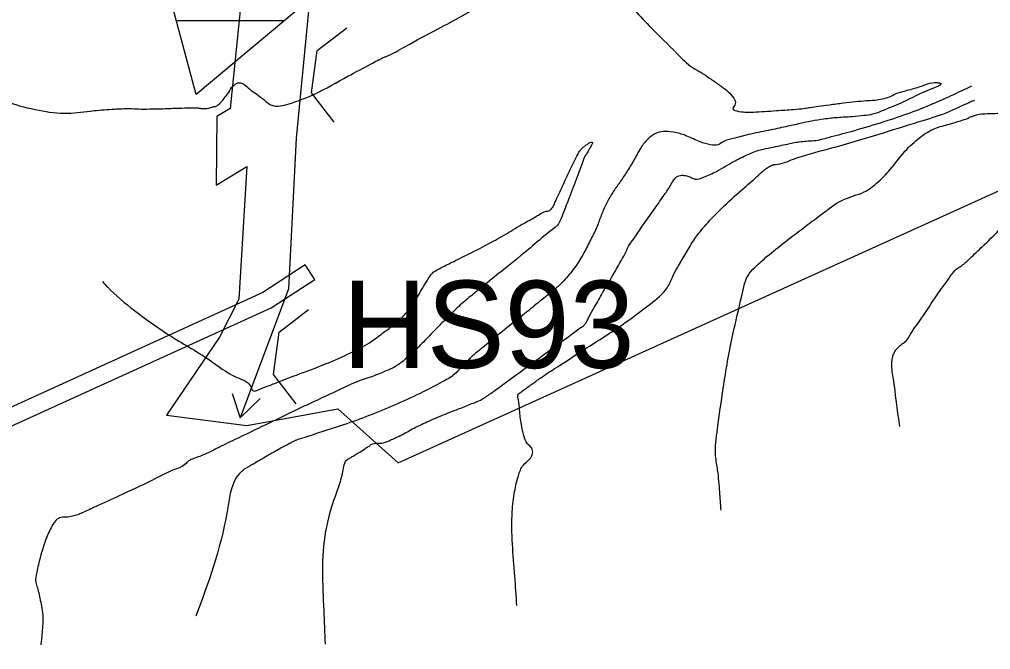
# Model space of a CAD drawing. Extents: x -478464 to -472469, y -1118040 to -1113785.
# Drawn here: x -476628.2 to -476517, y -1115298.9 to -1115226.7 of the extents above; entities that cross this region are included whole.
import ezdxf

# ---------------------------------------------------------------- set-up
doc = ezdxf.new("R2010")
doc.units = 0
for name, color, linetype in [('cestní_příkop_návrh', 7, 'Continuous'), ('hospodářské sjezdy', 7, 'Continuous'), ('meliorace', 7, 'Continuous'), ('ObPÚ', 7, 'Continuous'), ('vodní plochy', 7, 'Continuous'), ('Vrstevnice_hlavni', 7, 'Continuous'), ('Vrstevnice_vedlejsi', 7, 'Continuous')]:
    doc.layers.add(name, color=color, linetype=linetype)

msp = doc.modelspace()

# ---------------------------------------------------------------- linework, layer by layer
at = {"layer": 'cestní_příkop_návrh'}
for p, q in [((-476603.841, -1115269.537), (-476602.946, -1115272.292)), ((-476602.946, -1115272.292), (-476600.666, -1115270.108))]:
    msp.add_line(p, q, dxfattribs=at)
msp.add_lwpolyline([(-476592.877, -1115202.391), (-476596.533, -1115240.263), (-476597.4, -1115257.53), (-476602.946, -1115272.292)], dxfattribs=at)
at = {"layer": 'hospodářské sjezdy'}
for p, q in [((-476594.125, -1115230.214), (-476590.743, -1115227.615)), ((-476594.763, -1115235.058), (-476594.125, -1115230.214)), ((-476592.168, -1115238.443), (-476594.763, -1115235.058)), ((-476598.487, -1115262.482), (-476595.105, -1115259.884)), ((-476599.125, -1115267.326), (-476598.487, -1115262.482)), ((-476596.53, -1115270.711), (-476599.125, -1115267.326))]:
    msp.add_line(p, q, dxfattribs=at)
at = {"layer": 'meliorace'}
msp.add_line((-476610.243, -1115226.781), (-476597.848, -1115226.781), dxfattribs=at)
msp.add_lwpolyline([(-476265.52, -1115104.967), (-476403.006, -1115128.309), (-476504.597, -1115173.139), (-476570.859, -1115204.199), (-476607.972, -1115235.252), (-476617.925, -1115198.125), (-476654.773, -1115224.496), (-476674.466, -1115245.995), (-476697.623, -1115206.296), (-476764.621, -1115246.225), (-476786.533, -1115238.993), (-476834.366, -1115202.796)], dxfattribs=at)
at = {"layer": 'ObPÚ'}
msp.add_lwpolyline([(-476710.61, -1115306.79), (-476720.97, -1115296.87), (-476747.11, -1115275.54), (-476773.1, -1115256.26), (-476753.8, -1115247.81), (-476712.61, -1115214.58), (-476702.4, -1115206.29), (-476694.31, -1115201.09), (-476681.61, -1115192.9), (-476666.84, -1115216.01), (-476654.39, -1115235.55), (-476600.77, -1115204.27), (-476604.1, -1115236.86), (-476605.608, -1115237.767), (-476605.682, -1115245.637), (-476602.18, -1115243.52), (-476602.635, -1115251.11), (-476603.09, -1115258.7), (-476605.31, -1115263.08), (-476611.38, -1115272), (-476602.17, -1115273.19), (-476591.75, -1115271.28), (-476584.84, -1115277.47), (-476500.96, -1115239.45)], dxfattribs=at)
at = {"layer": 'vodní plochy'}
msp.add_line((-476594.388, -1115256.456), (-476595.478, -1115254.78), dxfattribs=at)
for points in [[(-476595.478, -1115254.78), (-476600.348, -1115257.945), (-476635.052, -1115273.742), (-476677.746, -1115288.446), (-476696.055, -1115299.721), (-476699.28, -1115302.082), (-476703.29, -1115304.179), (-476711.241, -1115309.034), (-476722.675, -1115317.101), (-476731.269, -1115323.918), (-476761.118, -1115341.041)], [(-476702.304, -1115305.921), (-476698.22, -1115303.784), (-476694.939, -1115301.383), (-476676.886, -1115290.264), (-476634.31, -1115275.602), (-476599.384, -1115259.703), (-476594.388, -1115256.456)]]:
    msp.add_lwpolyline(points, dxfattribs=at)
at = {"layer": 'Vrstevnice_hlavni'}
for points in [[(-476594.305, -1115212.433), (-476589.149, -1115215.617), (-476587.057, -1115217.102), (-476585.449, -1115218.483), (-476584.326, -1115219.757), (-476583.33, -1115220.543), (-476582.461, -1115220.842), (-476581.718, -1115220.652), (-476580.639, -1115220.531), (-476579.224, -1115220.478), (-476577.473, -1115220.493), (-476575.153, -1115219.941), (-476572.265, -1115218.82), (-476568.807, -1115217.132), (-476563.862, -1115214.927), (-476557.428, -1115212.206), (-476549.506, -1115208.968), (-476543.938, -1115207.11), (-476540.724, -1115206.632), (-476539.864, -1115207.534), (-476539.225, -1115208.173), (-476538.808, -1115208.549), (-476538.612, -1115208.662), (-476538.231, -1115208.929), (-476537.666, -1115209.347), (-476536.917, -1115209.919), (-476536.136, -1115210.322), (-476535.324, -1115210.556), (-476534.48, -1115210.622), (-476533.796, -1115210.6), (-476533.27, -1115210.49), (-476532.903, -1115210.292), (-476532.5, -1115210.146), (-476532.06, -1115210.051), (-476531.583, -1115210.008), (-476530.006, -1115210.808), (-476527.328, -1115212.452), (-476523.549, -1115214.939), (-476520.836, -1115216.731), (-476519.188, -1115217.826), (-476518.606, -1115218.224), (-476517.249, -1115217.693), (-476515.118, -1115216.231), (-476512.211, -1115213.838), (-476509.565, -1115211.741), (-476507.181, -1115209.94), (-476505.057, -1115208.433), (-476503.249, -1115207.018), (-476501.757, -1115205.694), (-476500.581, -1115204.461), (-476497.901, -1115203.024), (-476493.715, -1115201.384), (-476488.024, -1115199.541), (-476482.184, -1115197.217), (-476476.192, -1115194.414), (-476470.051, -1115191.13), (-476465.446, -1115188.696), (-476462.378, -1115187.113), (-476460.846, -1115186.38), (-476458.763, -1115185.408), (-476456.129, -1115184.199), (-476452.943, -1115182.751), (-476451.764, -1115182.586), (-476452.593, -1115183.704), (-476455.428, -1115186.103), (-476457.762, -1115188.052), (-476459.597, -1115189.55), (-476460.93, -1115190.598), (-476464.087, -1115193.012), (-476469.066, -1115196.792), (-476475.868, -1115201.939), (-476480.908, -1115205.899), (-476484.185, -1115208.674), (-476485.7, -1115210.262), (-476486.849, -1115211.737), (-476487.632, -1115213.098), (-476488.05, -1115214.346), (-476489.152, -1115215.928), (-476490.94, -1115217.844), (-476493.413, -1115220.094), (-476495.2, -1115221.825), (-476496.301, -1115223.037), (-476496.715, -1115223.731), (-476496.992, -1115224.194), (-476497.13, -1115224.425), (-476497.131, -1115224.425), (-476497.915, -1115225.146), (-476499.483, -1115226.587), (-476501.835, -1115228.749), (-476503.657, -1115230.272), (-476504.951, -1115231.155), (-476506.478, -1115231.643)], [(-476532.986, -1115239.492), (-476529.594, -1115238.495), (-476526.551, -1115237.472), (-476523.857, -1115236.425), (-476519.167, -1115234.282)], [(-476593.169, -1115298.22), (-476593.33, -1115294.354), (-476593.122, -1115285.305), (-476592.031, -1115281.263), (-476591.199, -1115278.509), (-476590.627, -1115277.043), (-476590.314, -1115276.865), (-476589.904, -1115276.621), (-476589.398, -1115276.313), (-476588.795, -1115275.94), (-476588.341, -1115275.65), (-476588.037, -1115275.443), (-476587.881, -1115275.319), (-476587.611, -1115275.238), (-476587.225, -1115275.201), (-476586.725, -1115275.206), (-476585.892, -1115274.939), (-476584.727, -1115274.398), (-476583.23, -1115273.584), (-476581.554, -1115272.777), (-476579.698, -1115271.976), (-476577.664, -1115271.182), (-476576.234, -1115270.611), (-476575.407, -1115270.264), (-476575.184, -1115270.141), (-476574.915, -1115269.974), (-476574.601, -1115269.763), (-476574.242, -1115269.509), (-476572.91, -1115268.538), (-476570.606, -1115266.85), (-476567.33, -1115264.446), (-476565.075, -1115262.798), (-476563.843, -1115261.906), (-476563.633, -1115261.77), (-476563.42, -1115261.532), (-476563.205, -1115261.193), (-476562.988, -1115260.753), (-476562.395, -1115259.684), (-476561.428, -1115257.985), (-476560.085, -1115255.656), (-476559.161, -1115254.025), (-476558.654, -1115253.092), (-476558.566, -1115252.857), (-476558.004, -1115251.986), (-476556.968, -1115250.48), (-476555.459, -1115248.339), (-476554.354, -1115246.737), (-476553.653, -1115245.675), (-476553.355, -1115245.151), (-476553.038, -1115244.784), (-476552.702, -1115244.573), (-476552.345, -1115244.517), (-476551.924, -1115244.561), (-476551.439, -1115244.705), (-476550.889, -1115244.949), (-476549.877, -1115244.74), (-476548.405, -1115244.078), (-476546.472, -1115242.962), (-476544.787, -1115242.135), (-476543.349, -1115241.596), (-476542.158, -1115241.344), (-476541.144, -1115241.128), (-476540.305, -1115240.947), (-476539.641, -1115240.801), (-476538.91, -1115240.685), (-476538.112, -1115240.6), (-476537.245, -1115240.545), (-476535.537, -1115240.176), (-476532.986, -1115239.492)]]:
    msp.add_spline(points, degree=3, dxfattribs=at)
at = {"layer": 'Vrstevnice_vedlejsi'}
for points in [[(-476527.08, -1115263.803), (-476526.887, -1115263.69), (-476526.162, -1115262.721), (-476524.907, -1115260.894), (-476523.121, -1115258.209), (-476521.764, -1115256.313), (-476520.836, -1115255.206), (-476520.337, -1115254.886), (-476519.366, -1115254.043), (-476517.924, -1115252.676), (-476516.009, -1115250.786), (-476514.302, -1115249.024), (-476512.803, -1115247.392), (-476511.511, -1115245.89), (-476509.929, -1115244.508), (-476508.058, -1115243.246), (-476505.898, -1115242.105), (-476504.014, -1115241.274), (-476502.406, -1115240.753), (-476501.074, -1115240.543), (-476500.026, -1115240.386), (-476499.263, -1115240.283), (-476498.784, -1115240.233), (-476497.172, -1115239.574), (-476494.427, -1115238.305), (-476490.549, -1115236.427), (-476487.653, -1115234.652), (-476485.739, -1115232.982), (-476484.807, -1115231.416), (-476483.874, -1115229.496), (-476482.938, -1115227.221), (-476482, -1115224.593), (-476480.343, -1115222.339), (-476477.964, -1115220.46), (-476474.866, -1115218.956), (-476472.042, -1115216.696), (-476469.492, -1115213.68), (-476467.217, -1115209.908), (-476464.704, -1115205.831), (-476461.955, -1115201.448), (-476458.968, -1115196.76), (-476456.464, -1115193.232), (-476454.442, -1115190.863), (-476452.903, -1115189.654), (-476451.796, -1115188.78), (-476451.122, -1115188.24), (-476450.88, -1115188.036), (-476449.741, -1115187.407), (-476447.705, -1115186.353), (-476444.771, -1115184.875), (-476442.444, -1115183.754), (-476440.723, -1115182.99), (-476439.608, -1115182.582), (-476438.521, -1115182.379), (-476437.462, -1115182.381), (-476436.431, -1115182.589), (-476434.671, -1115182.945), (-476432.182, -1115183.449), (-476428.964, -1115184.102), (-476425.887, -1115183.927), (-476422.953, -1115182.925), (-476420.161, -1115181.095), (-476418.073, -1115179.463), (-476416.69, -1115178.026), (-476416.012, -1115176.786), (-476414.938, -1115175.626), (-476413.47, -1115174.546), (-476411.607, -1115173.546), (-476409.534, -1115172.603), (-476407.252, -1115171.715), (-476404.761, -1115170.883), (-476401.574, -1115169.794), (-476397.69, -1115168.447), (-476393.11, -1115166.843), (-476388.096, -1115165.135), (-476382.647, -1115163.324), (-476376.764, -1115161.408), (-476372.621, -1115160.054), (-476370.219, -1115159.261), (-476369.557, -1115159.028), (-476369.039, -1115158.854), (-476368.663, -1115158.738), (-476368.431, -1115158.68), (-476367.559, -1115158.618), (-476366.047, -1115158.551), (-476363.896, -1115158.479), (-476362.463, -1115158.431), (-476361.747, -1115158.407), (-476361.748, -1115158.407), (-476361.852, -1115158.365), (-476362.059, -1115158.28), (-476362.368, -1115158.152), (-476365.304, -1115157.405), (-476370.868, -1115156.037), (-476379.058, -1115154.05), (-476384.846, -1115152.681), (-476388.232, -1115151.932)], [(-476489.189, -1115228.952), (-476487.784, -1115226.601), (-476486.814, -1115225.003), (-476486.28, -1115224.159), (-476486.181, -1115224.07), (-476485.87, -1115223.275), (-476485.346, -1115221.777), (-476484.609, -1115219.573), (-476483.875, -1115217.426), (-476483.145, -1115215.334), (-476482.419, -1115213.299), (-476481.856, -1115211.903), (-476481.455, -1115211.148), (-476481.216, -1115211.032), (-476480.998, -1115210.858), (-476480.802, -1115210.625), (-476480.626, -1115210.334), (-476480.433, -1115210.02), (-476480.221, -1115209.682), (-476479.991, -1115209.321), (-476476.937, -1115206.803), (-476471.061, -1115202.128), (-476462.362, -1115195.296), (-476456.107, -1115190.356), (-476452.296, -1115187.307), (-476450.93, -1115186.151), (-476449.375, -1115185.055), (-476447.634, -1115184.022), (-476445.704, -1115183.05), (-476443.654, -1115182.122), (-476441.483, -1115181.239), (-476439.191, -1115180.401), (-476436.957, -1115179.984), (-476434.78, -1115179.989), (-476432.661, -1115180.416), (-476430.764, -1115180.799), (-476429.089, -1115181.137), (-476427.637, -1115181.432), (-476426.249, -1115181.353), (-476424.924, -1115180.901), (-476423.664, -1115180.075), (-476422.478, -1115178.892), (-476421.365, -1115177.35), (-476420.326, -1115175.451), (-476418.682, -1115173.674), (-476416.432, -1115172.02), (-476413.578, -1115170.488), (-476411.336, -1115169.353), (-476409.707, -1115168.616), (-476408.69, -1115168.277), (-476405.909, -1115167.314), (-476401.362, -1115165.727), (-476395.051, -1115163.517), (-476390.685, -1115161.991), (-476388.263, -1115161.15), (-476387.785, -1115160.995), (-476387.676, -1115160.76), (-476387.937, -1115160.445), (-476388.566, -1115160.051), (-476389.672, -1115159.551), (-476391.253, -1115158.946), (-476393.311, -1115158.235), (-476397.324, -1115158.048), (-476403.292, -1115158.382), (-476411.216, -1115159.239), (-476416.651, -1115159.884), (-476419.597, -1115160.315), (-476420.053, -1115160.534), (-476420.464, -1115160.658), (-476420.831, -1115160.689), (-476421.152, -1115160.625), (-476422.489, -1115160.766), (-476424.841, -1115161.111), (-476428.208, -1115161.661), (-476433.237, -1115162.642), (-476439.928, -1115164.054), (-476448.281, -1115165.897), (-476454.566, -1115167.346), (-476458.784, -1115168.401), (-476460.934, -1115169.061), (-476463.942, -1115170.404), (-476467.808, -1115172.43), (-476472.532, -1115175.139), (-476478.16, -1115177.4), (-476484.692, -1115179.212), (-476492.129, -1115180.577), (-476497.835, -1115181.563), (-476501.811, -1115182.17), (-476504.055, -1115182.398), (-476506.213, -1115182.703), (-476508.286, -1115183.083), (-476510.272, -1115183.54), (-476513.324, -1115184.328), (-476517.442, -1115185.448), (-476522.626, -1115186.898), (-476526.704, -1115187.828), (-476529.674, -1115188.238)], [(-476651.7, -1115230.934), (-476650.79, -1115230.806), (-476649.193, -1115230.886), (-476646.909, -1115231.176), (-476643.939, -1115231.674), (-476641.52, -1115232.103), (-476639.653, -1115232.461), (-476638.338, -1115232.748), (-476636.207, -1115233.456), (-476633.26, -1115234.585), (-476629.496, -1115236.133), (-476625.982, -1115237.071), (-476622.717, -1115237.398), (-476619.701, -1115237.114), (-476617.342, -1115236.939), (-476615.64, -1115236.874), (-476614.595, -1115236.918), (-476613.302, -1115236.924), (-476611.761, -1115236.892), (-476609.972, -1115236.821), (-476608.635, -1115236.794), (-476607.751, -1115236.811), (-476607.319, -1115236.872), (-476606.93, -1115236.882), (-476606.584, -1115236.842), (-476606.282, -1115236.752), (-476606.035, -1115236.683), (-476605.843, -1115236.637), (-476605.707, -1115236.613), (-476605.533, -1115236.512), (-476605.322, -1115236.336), (-476605.074, -1115236.084), (-476604.731, -1115235.659), (-476604.295, -1115235.063), (-476603.765, -1115234.294), (-476603.211, -1115233.942), (-476602.633, -1115234.007), (-476602.033, -1115234.488), (-476601.279, -1115235.063), (-476600.374, -1115235.732), (-476599.315, -1115236.495), (-476597.335, -1115236.323), (-476594.433, -1115235.215), (-476590.609, -1115233.172), (-476587.951, -1115231.767), (-476586.458, -1115231.001), (-476586.131, -1115230.873), (-476584.069, -1115229.787), (-476580.272, -1115227.744), (-476574.742, -1115224.743), (-476570.474, -1115222.455), (-476567.471, -1115220.879), (-476565.732, -1115220.017), (-476564.567, -1115219.442), (-476563.977, -1115219.155), (-476563.962, -1115219.156), (-476563.93, -1115219.191), (-476563.881, -1115219.258), (-476563.815, -1115219.359), (-476563.749, -1115219.439), (-476563.682, -1115219.497), (-476563.615, -1115219.535), (-476562.287, -1115220.905), (-476559.697, -1115223.61), (-476555.845, -1115227.647), (-476552.971, -1115230.517), (-476551.073, -1115232.219), (-476550.152, -1115232.753), (-476549.173, -1115233.387), (-476548.137, -1115234.121), (-476547.043, -1115234.955), (-476546.409, -1115235.694), (-476546.234, -1115236.339), (-476546.52, -1115236.89), (-476545.831, -1115237.202), (-476544.169, -1115237.276), (-476541.532, -1115237.113), (-476539.572, -1115236.97), (-476538.288, -1115236.848), (-476537.68, -1115236.746), (-476536.739, -1115236.61), (-476535.466, -1115236.44), (-476533.859, -1115236.236), (-476532.457, -1115236.078), (-476531.259, -1115235.968), (-476530.265, -1115235.905), (-476529.373, -1115235.756), (-476528.581, -1115235.523), (-476527.891, -1115235.203), (-476526.752, -1115234.828), (-476525.166, -1115234.395), (-476523.131, -1115233.905), (-476522.686, -1115233.995), (-476523.832, -1115234.666), (-476526.569, -1115235.916), (-476528.598, -1115236.81), (-476529.918, -1115237.347)], [(-476547.866, -1115282.869), (-476548.02, -1115280.793), (-476548.258, -1115278.295), (-476548.49, -1115276.677), (-476548.277, -1115273.545), (-476547.617, -1115268.9), (-476546.512, -1115262.741), (-476545.505, -1115258.348), (-476544.597, -1115255.721), (-476543.788, -1115254.861), (-476542.361, -1115253.614), (-476540.317, -1115251.98), (-476537.656, -1115249.96), (-476535.763, -1115248.543), (-476534.636, -1115247.729), (-476534.277, -1115247.519), (-476533.628, -1115247.233), (-476532.69, -1115246.871), (-476531.463, -1115246.432), (-476530.073, -1115245.436), (-476528.521, -1115243.881), (-476526.805, -1115241.769), (-476525.095, -1115240.194), (-476523.391, -1115239.157), (-476521.692, -1115238.657), (-476520.443, -1115238.271), (-476519.644, -1115237.998), (-476519.294, -1115237.838), (-476518.955, -1115237.707), (-476518.628, -1115237.605), (-476518.312, -1115237.532), (-476517.034, -1115237.443), (-476514.795, -1115237.337), (-476511.594, -1115237.214), (-476507.502, -1115236.507), (-476502.517, -1115235.215), (-476496.641, -1115233.338), (-476492.705, -1115232.069), (-476490.708, -1115231.408), (-476490.652, -1115231.356), (-476490.145, -1115230.537), (-476489.189, -1115228.952)], [(-476570.497, -1115269.135), (-476569.912, -1115268.721), (-476569.411, -1115268.363), (-476568.994, -1115268.062), (-476568.662, -1115267.818), (-476566.925, -1115266.673), (-476563.786, -1115264.628), (-476559.243, -1115261.683), (-476555.997, -1115259.281), (-476554.049, -1115257.421), (-476553.398, -1115256.105), (-476552.637, -1115254.705), (-476551.765, -1115253.222), (-476550.783, -1115251.655), (-476549.361, -1115249.918), (-476547.499, -1115248.009), (-476545.197, -1115245.93), (-476543.564, -1115244.487), (-476542.599, -1115243.68), (-476542.304, -1115243.509), (-476542.087, -1115243.392), (-476541.951, -1115243.327), (-476541.893, -1115243.315), (-476541.845, -1115243.304), (-476541.804, -1115243.295), (-476541.772, -1115243.288), (-476541.737, -1115243.283), (-476541.699, -1115243.279), (-476541.657, -1115243.276), (-476539.572, -1115242.669), (-476535.443, -1115241.458), (-476529.27, -1115239.643), (-476524.705, -1115238.227), (-476521.746, -1115237.21), (-476520.394, -1115236.592), (-476519.469, -1115236.175), (-476518.97, -1115235.958), (-476518.826, -1115235.924)], [(-476529.918, -1115237.347), (-476530.529, -1115237.526), (-476531.501, -1115237.682), (-476532.833, -1115237.814), (-476534.524, -1115237.921), (-476536.083, -1115238.088), (-476537.511, -1115238.314), (-476538.805, -1115238.598), (-476540.443, -1115238.952), (-476542.423, -1115239.374), (-476544.747, -1115239.865), (-476546.486, -1115240.302), (-476547.642, -1115240.685), (-476548.213, -1115241.015), (-476549.092, -1115241.015), (-476550.277, -1115240.684), (-476551.769, -1115240.023), (-476553.085, -1115239.632), (-476554.226, -1115239.513), (-476555.192, -1115239.664), (-476556.105, -1115240.237), (-476556.964, -1115241.233), (-476557.77, -1115242.651), (-476558.574, -1115243.973), (-476559.374, -1115245.2), (-476560.171, -1115246.331), (-476560.867, -1115247.524), (-476561.462, -1115248.778), (-476561.957, -1115250.094), (-476562.594, -1115251.504), (-476563.373, -1115253.008), (-476564.295, -1115254.607), (-476565.404, -1115256.074), (-476566.701, -1115257.411), (-476568.186, -1115258.616), (-476569.891, -1115259.994), (-476571.816, -1115261.544), (-476573.961, -1115263.266), (-476575.502, -1115264.525), (-476576.44, -1115265.32), (-476576.773, -1115265.651), (-476577.208, -1115266.091), (-476577.745, -1115266.64), (-476578.382, -1115267.299), (-476579.789, -1115268.193), (-476581.966, -1115269.324), (-476584.912, -1115270.69), (-476587.833, -1115271.911), (-476590.73, -1115272.984), (-476593.601, -1115273.912), (-476595.552, -1115274.547), (-476596.58, -1115274.891), (-476596.688, -1115274.942), (-476596.825, -1115275.01), (-476596.991, -1115275.095), (-476597.186, -1115275.196), (-476597.317, -1115275.263), (-476597.382, -1115275.297), (-476597.608, -1115275.419), (-476598.059, -1115275.664), (-476598.737, -1115276.032), (-476599.311, -1115276.353), (-476599.784, -1115276.628), (-476600.154, -1115276.857), (-476600.743, -1115277.205), (-476601.549, -1115277.67), (-476602.574, -1115278.254), (-476604.448, -1115283.053), (-476608.008, -1115295.009)], [(-476618.696, -1115256.706), (-476618.139, -1115257.317), (-476615.04, -1115260.001), (-476611.15, -1115262.782), (-476606.47, -1115265.66), (-476603.314, -1115267.67), (-476601.684, -1115268.812), (-476601.579, -1115269.085), (-476601.411, -1115269.224), (-476601.18, -1115269.231), (-476600.886, -1115269.103), (-476600.612, -1115268.988), (-476600.357, -1115268.884), (-476600.122, -1115268.793), (-476598.831, -1115268.297), (-476596.482, -1115267.399), (-476593.077, -1115266.096), (-476590.299, -1115264.864), (-476588.147, -1115263.702), (-476586.622, -1115262.61), (-476585.462, -1115261.734), (-476584.668, -1115261.075), (-476584.239, -1115260.633), (-476583.831, -1115260.159), (-476583.444, -1115259.654), (-476583.078, -1115259.118), (-476582.651, -1115258.45), (-476582.162, -1115257.65), (-476581.613, -1115256.718), (-476581.166, -1115256.042), (-476580.821, -1115255.622), (-476580.579, -1115255.459), (-476579.737, -1115255.014), (-476578.294, -1115254.289), (-476576.249, -1115253.282), (-476574.221, -1115252.212), (-476572.208, -1115251.08), (-476570.212, -1115249.885), (-476568.776, -1115249.072), (-476567.902, -1115248.64), (-476567.588, -1115248.589), (-476567.306, -1115248.385), (-476567.056, -1115248.028), (-476566.838, -1115247.516), (-476566.421, -1115246.601), (-476565.804, -1115245.283), (-476564.987, -1115243.561), (-476564.368, -1115242.334), (-476563.945, -1115241.6), (-476563.72, -1115241.362), (-476563.448, -1115241.136), (-476563.129, -1115240.923), (-476562.763, -1115240.724), (-476562.609, -1115240.748), (-476562.666, -1115240.996), (-476562.935, -1115241.468), (-476563.142, -1115241.823), (-476563.288, -1115242.061), (-476563.373, -1115242.182), (-476563.73, -1115243.061), (-476564.359, -1115244.699), (-476565.26, -1115247.095), (-476565.916, -1115248.788), (-476566.326, -1115249.778), (-476566.492, -1115250.066), (-476567.617, -1115251.081), (-476569.702, -1115252.825), (-476572.747, -1115255.297), (-476574.988, -1115257.114), (-476576.425, -1115258.278), (-476577.058, -1115258.786), (-476577.733, -1115259.376), (-476578.45, -1115260.048), (-476579.208, -1115260.801), (-476580.197, -1115261.802), (-476581.417, -1115263.051)], [(-476581.417, -1115263.051), (-476582.867, -1115264.548), (-476584.154, -1115265.695), (-476585.279, -1115266.492), (-476586.242, -1115266.939), (-476587.197, -1115267.337), (-476588.144, -1115267.688), (-476589.082, -1115267.991), (-476591.371, -1115268.993), (-476595.011, -1115270.693), (-476600.002, -1115273.091), (-476603.548, -1115274.803), (-476605.648, -1115275.828), (-476606.303, -1115276.166), (-476606.945, -1115276.464), (-476607.574, -1115276.722), (-476608.189, -1115276.94), (-476608.655, -1115277.147), (-476608.972, -1115277.344), (-476609.139, -1115277.53), (-476610.496, -1115278.239), (-476613.043, -1115279.471), (-476616.781, -1115281.225), (-476619.444, -1115282.466), (-476621.031, -1115283.195), (-476621.543, -1115283.411), (-476622.145, -1115283.575), (-476622.837, -1115283.688), (-476623.62, -1115283.749), (-476624.38, -1115284.537), (-476625.117, -1115286.051), (-476625.832, -1115288.292), (-476626.244, -1115289.997), (-476626.355, -1115291.165), (-476626.163, -1115291.796), (-476625.973, -1115292.543), (-476625.785, -1115293.405), (-476625.598, -1115294.384), (-476625.751, -1115298.174), (-476625.761, -1115298.309)], [(-476527.386, -1115273.295), (-476527.744, -1115270.859), (-476528.147, -1115267.674), (-476528.303, -1115265.828), (-476528.212, -1115265.322), (-476528.057, -1115264.885), (-476527.839, -1115264.516), (-476527.556, -1115264.216), (-476527.303, -1115263.978), (-476527.08, -1115263.803)], [(-476571.258, -1115293.805), (-476571.484, -1115290.467), (-476571.781, -1115283.048), (-476571.507, -1115280.729), (-476571.081, -1115278.95), (-476570.504, -1115277.713), (-476569.776, -1115277.016), (-476569.456, -1115276.376), (-476569.544, -1115275.794), (-476570.04, -1115275.27), (-476570.438, -1115274.362), (-476570.739, -1115273.07), (-476570.941, -1115271.395), (-476571.069, -1115270.26), (-476571.123, -1115269.664), (-476571.103, -1115269.607), (-476570.894, -1115269.43), (-476570.497, -1115269.135)]]:
    msp.add_spline(points, degree=3, dxfattribs=at)

# ---------------------------------------------------------------- texts
at = {"layer": 'hospodářské sjezdy'}
msp.add_text('HS93', height=10, rotation=359.99999, dxfattribs=at).set_placement((-476591.231, -1115266.596))

doc.saveas('drawing.dxf')
